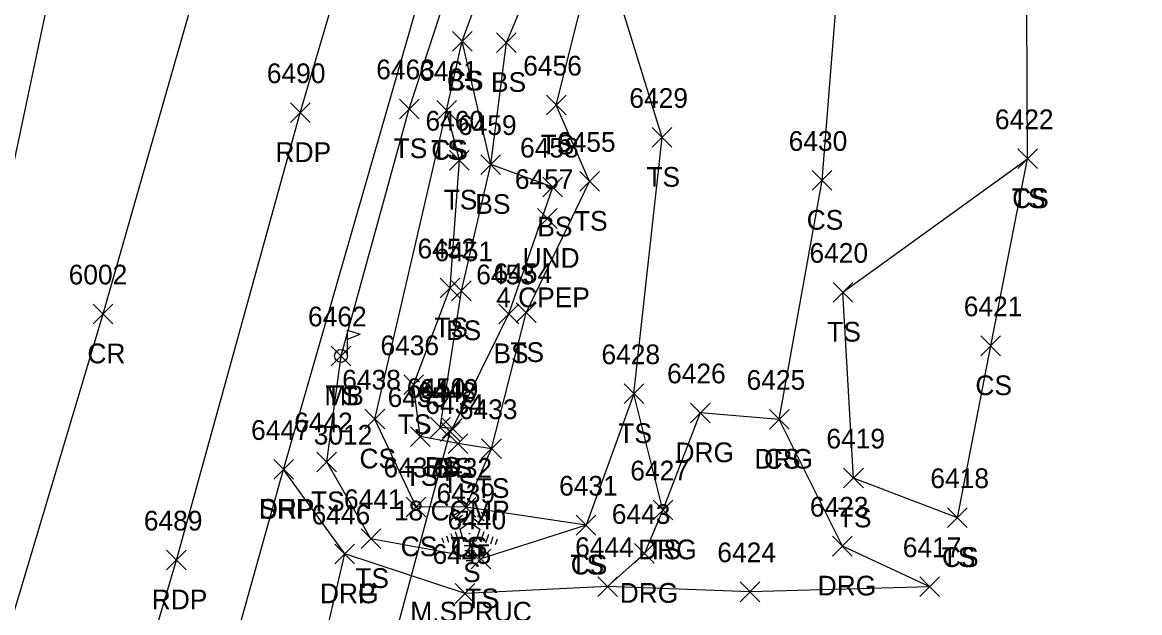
# Model space of a CAD drawing. Extents: x 1443912 to 1445411, y 621446 to 623693.
# Drawn here: x 1444581.9 to 1444695.3, y 621993.5 to 622053.4 of the extents above; entities that cross this region are included whole.
import ezdxf

# ---------------------------------------------------------------- set-up
doc = ezdxf.new("R2010")
doc.units = 0
for name, color, linetype in [('D_A', 7, 'Continuous'), ('D_C', 7, 'Continuous'), ('D_I', 7, 'Continuous'), ('D_TIC', 7, 'Continuous'), ('DCP', 7, 'Continuous'), ('L_A', 7, 'Continuous'), ('L_C', 7, 'Continuous'), ('L_I', 7, 'Continuous'), ('L_TIC', 7, 'Continuous'), ('LELB', 7, 'Continuous'), ('LMB', 7, 'Continuous'), ('LTC', 7, 'Continuous'), ('P_A', 7, 'Continuous'), ('P_I', 7, 'Continuous'), ('P_TIC', 7, 'Continuous'), ('PET', 7, 'Continuous'), ('PRC', 7, 'Continuous'), ('PSP', 7, 'Continuous'), ('R_A', 7, 'Continuous'), ('R_I', 7, 'Continuous'), ('R_TIC', 7, 'Continuous'), ('RDG', 7, 'Continuous'), ('RDP', 7, 'Continuous')]:
    doc.layers.add(name, color=color, linetype=linetype)

msp = doc.modelspace()

# ---------------------------------------------------------------- linework, layer by layer
at = {"layer": 'D_TIC'}
for points in [[(1444634.23, 622032.46), (1444636.23, 622034.46)], [(1444636.23, 622032.46), (1444634.23, 622034.46)], [(1444624.36, 622010.83), (1444626.36, 622012.83)], [(1444626.36, 622010.83), (1444624.36, 622012.83)]]:
    msp.add_lwpolyline(points, dxfattribs=at)
at = {"layer": 'DCP'}
msp.add_lwpolyline([(1444615.47, 621975.13), (1444625.36, 622011.83)], dxfattribs=at)
at = {"layer": 'L_TIC'}
for points in [[(1444625.59, 622050.44), (1444627.59, 622052.44)], [(1444627.59, 622050.44), (1444625.59, 622052.44)], [(1444625.59, 622050.44), (1444627.59, 622052.44)], [(1444627.59, 622050.44), (1444625.59, 622052.44)], [(1444630.06, 622050.3), (1444632.06, 622052.3)], [(1444632.06, 622050.3), (1444630.06, 622052.3)], [(1444620.21, 622043.58), (1444622.21, 622045.58)], [(1444622.21, 622043.58), (1444620.21, 622045.58)], [(1444635.13, 622043.96), (1444637.13, 622045.96)], [(1444637.13, 622043.96), (1444635.13, 622045.96)], [(1444624, 622043.42), (1444626, 622045.42)], [(1444626, 622043.42), (1444624, 622045.42)], [(1444624, 622043.42), (1444626, 622045.42)], [(1444626, 622043.42), (1444624, 622045.42)], [(1444645.86, 622040.68), (1444647.86, 622042.68)], [(1444647.86, 622040.68), (1444645.86, 622042.68)], [(1444625.29, 622038.37), (1444627.29, 622040.37)], [(1444627.29, 622038.37), (1444625.29, 622040.37)], [(1444628.47, 622037.93), (1444630.47, 622039.93)], [(1444630.47, 622037.93), (1444628.47, 622039.93)], [(1444628.47, 622037.93), (1444630.47, 622039.93)], [(1444630.47, 622037.93), (1444628.47, 622039.93)], [(1444682.95, 622038.52), (1444684.95, 622040.52)], [(1444684.95, 622038.52), (1444682.95, 622040.52)], [(1444682.95, 622038.52), (1444684.95, 622040.52)], [(1444684.95, 622038.52), (1444682.95, 622040.52)], [(1444634.76, 622035.64), (1444636.76, 622037.64)], [(1444636.76, 622035.64), (1444634.76, 622037.64)], [(1444638.51, 622036.22), (1444640.51, 622038.22)], [(1444640.51, 622036.22), (1444638.51, 622038.22)], [(1444662.1, 622036.32), (1444664.1, 622038.32)], [(1444664.1, 622036.32), (1444662.1, 622038.32)], [(1444624.35, 622025.41), (1444626.35, 622027.41)], [(1444626.35, 622025.41), (1444624.35, 622027.41)], [(1444625.5, 622025.12), (1444627.5, 622027.12)], [(1444627.5, 622025.12), (1444625.5, 622027.12)], [(1444664.22, 622024.97), (1444666.22, 622026.97)], [(1444666.22, 622024.97), (1444664.22, 622026.97)], [(1444630.31, 622022.78), (1444632.31, 622024.78)], [(1444632.31, 622022.78), (1444630.31, 622024.78)], [(1444632.07, 622022.9), (1444634.07, 622024.9)], [(1444634.07, 622022.9), (1444632.07, 622024.9)], [(1444679.22, 622019.54), (1444681.22, 622021.54)], [(1444681.22, 622019.54), (1444679.22, 622021.54)], [(1444613.28, 622018.52), (1444615.28, 622020.52)], [(1444615.28, 622018.52), (1444613.28, 622020.52)], [(1444620.64, 622015.59), (1444622.64, 622017.59)], [(1444622.64, 622015.59), (1444620.64, 622017.59)], [(1444643.01, 622014.68), (1444645.01, 622016.68)], [(1444645.01, 622014.68), (1444643.01, 622016.68)], [(1444643.01, 622014.68), (1444645.01, 622016.68)], [(1444645.01, 622014.68), (1444643.01, 622016.68)], [(1444616.71, 622012.11), (1444618.71, 622014.11)], [(1444618.71, 622012.11), (1444616.71, 622014.11)], [(1444657.75, 622012.08), (1444659.75, 622014.08)], [(1444659.75, 622012.08), (1444657.75, 622014.08)], [(1444623.35, 622011.26), (1444625.35, 622013.26)], [(1444625.35, 622011.26), (1444623.35, 622013.26)], [(1444624.58, 622011.17), (1444626.58, 622013.17)], [(1444626.58, 622011.17), (1444624.58, 622013.17)], [(1444624.58, 622011.17), (1444626.58, 622013.17)], [(1444626.58, 622011.17), (1444624.58, 622013.17)], [(1444621.32, 622010.34), (1444623.32, 622012.34)], [(1444623.32, 622010.34), (1444621.32, 622012.34)], [(1444625.14, 622009.63), (1444627.14, 622011.63)], [(1444627.14, 622009.63), (1444625.14, 622011.63)], [(1444628.55, 622009.11), (1444630.55, 622011.11)], [(1444630.55, 622009.11), (1444628.55, 622011.11)], [(1444628.55, 622009.11), (1444630.55, 622011.11)], [(1444630.55, 622009.11), (1444628.55, 622011.11)], [(1444611.83, 622007.77), (1444613.83, 622009.77)], [(1444613.83, 622007.77), (1444611.83, 622009.77)], [(1444665.29, 622006.13), (1444667.29, 622008.13)], [(1444667.29, 622006.13), (1444665.29, 622008.13)], [(1444620.9, 622003.2), (1444622.9, 622005.2)], [(1444622.9, 622003.2), (1444620.9, 622005.2)], [(1444625.96, 622003.16), (1444627.96, 622005.16)], [(1444627.96, 622003.16), (1444625.96, 622005.16)], [(1444625.96, 622003.16), (1444627.96, 622005.16)], [(1444627.96, 622003.16), (1444625.96, 622005.16)], [(1444645.95, 622002.89), (1444647.95, 622004.89)], [(1444647.95, 622002.89), (1444645.95, 622004.89)], [(1444675.83, 622002.11), (1444677.83, 622004.11)], [(1444677.83, 622002.11), (1444675.83, 622004.11)], [(1444675.83, 622002.11), (1444677.83, 622004.11)], [(1444677.83, 622002.11), (1444675.83, 622004.11)], [(1444638.15, 622001.35), (1444640.15, 622003.35)], [(1444640.15, 622001.35), (1444638.15, 622003.35)], [(1444638.15, 622001.35), (1444640.15, 622003.35)], [(1444640.15, 622001.35), (1444638.15, 622003.35)], [(1444616.32, 621999.98), (1444618.32, 622001.98)], [(1444618.32, 621999.98), (1444616.32, 622001.98)], [(1444627.48, 621997.92), (1444629.48, 621999.92)], [(1444629.48, 621997.92), (1444627.48, 621999.92)]]:
    msp.add_lwpolyline(points, dxfattribs=at)
at = {"layer": 'LELB'}
for points in [[(1444644.01, 622015.68), (1444639.15, 622002.35), (1444628.48, 621998.92), (1444617.32, 622000.98), (1444612.83, 622008.77), (1444614.28, 622019.52), (1444621.21, 622044.58), (1444632.46, 622078.99), (1444638.16, 622089.94), (1444643.22, 622097.1), (1444651.63, 622103.86), (1444671.66, 622102.03), (1444685.79, 622100.42), (1444698.09, 622093.83)], [(1444625.58, 622012.17), (1444631.31, 622023.78), (1444635.76, 622036.64), (1444629.47, 622038.93), (1444631.06, 622051.3), (1444637.11, 622065.66), (1444641.14, 622072.33), (1444643.26, 622087.97), (1444647.46, 622094.16), (1444644.74, 622096.3)], [(1444626.96, 622004.16), (1444629.55, 622010.11), (1444633.07, 622023.9), (1444639.51, 622037.22), (1444636.13, 622044.96), (1444640.48, 622062.36), (1444645.82, 622067.12), (1444646.95, 622073.59), (1444654.32, 622091.95), (1444676.1, 622093.86), (1444692.82, 622085.1)], [(1444625.58, 622012.17), (1444624.35, 622012.26), (1444626.5, 622026.12), (1444629.47, 622038.93), (1444626.59, 622051.44), (1444636.28, 622077.9), (1444640.86, 622088.53)], [(1444658.75, 622013.08), (1444663.1, 622037.32), (1444665.26, 622064.61)], [(1444646.95, 622003.89), (1444644.01, 622015.68), (1444646.86, 622041.68), (1444640.48, 622062.36)], [(1444676.83, 622003.11), (1444680.22, 622020.54), (1444683.95, 622039.52), (1444683.84, 622062.37)], [(1444639.15, 622002.35), (1444626.96, 622004.16), (1444621.9, 622004.2), (1444617.71, 622013.11), (1444625, 622044.42), (1444626.59, 622051.44)], [(1444629.55, 622010.11), (1444626.14, 622010.63), (1444622.32, 622011.34), (1444621.64, 622016.59), (1444625.35, 622026.41), (1444626.29, 622039.37), (1444625, 622044.42)], [(1444676.83, 622003.11), (1444666.29, 622007.13), (1444665.22, 622025.97), (1444683.95, 622039.52)]]:
    msp.add_lwpolyline(points, dxfattribs=at)
at = {"layer": 'LMB'}
for p, q in [((1444614.93, 622022.12), (1444616.23, 622021.74)), ((1444614.94, 622019.53), (1444614.94, 622022.12)), ((1444614.94, 622021.22), (1444616.22, 622021.73)), ((1444614.28, 622019.52), (1444614.28, 622019.52))]:
    msp.add_line(p, q, dxfattribs=at)
msp.add_circle((1444614.28, 622019.52), 0.656, dxfattribs=at)
at = {"layer": 'LTC'}
for p, q in [((1444625.48, 622003.79), (1444625.84, 622004.04)), ((1444625.69, 622003.32), (1444626.22, 622003.7)), ((1444628.51, 622003.68), (1444629.06, 622003.28)), ((1444628.88, 622004.03), (1444629.3, 622003.72)), ((1444625.9, 622002.85), (1444626.61, 622003.37)), ((1444626.11, 622002.39), (1444626.99, 622003.03)), ((1444626.34, 622001.93), (1444627.35, 622002.67)), ((1444627.35, 622002.67), (1444628.35, 622001.94)), ((1444627.77, 622002.98), (1444628.58, 622002.39)), ((1444628.14, 622003.33), (1444628.82, 622002.84)), ((1444625.43, 622001.5), (1444625.7, 622000.66)), ((1444625.88, 622001.71), (1444626.21, 622000.7)), ((1444626.34, 622001.93), (1444626.72, 622000.74)), ((1444628.35, 622001.94), (1444627.96, 622000.74)), ((1444628.78, 622001.67), (1444628.45, 622000.63)), ((1444629.23, 622001.42), (1444628.94, 622000.54)), ((1444624.52, 622001.06), (1444624.67, 622000.6)), ((1444624.97, 622001.28), (1444625.18, 622000.63)), ((1444627.96, 622000.74), (1444626.72, 622000.74)), ((1444627.92, 622000.24), (1444626.77, 622000.24)), ((1444629.67, 622001.17), (1444629.44, 622000.44)), ((1444630.12, 622000.92), (1444629.93, 622000.35)), ((1444627.83, 621999.74), (1444626.84, 621999.74)), ((1444627.75, 621999.24), (1444626.92, 621999.24)), ((1444627.67, 621998.74), (1444626.99, 621998.74))]:
    msp.add_line(p, q, dxfattribs=at)
at = {"layer": 'P_TIC'}
for points in [[(1444609.14, 622043.19), (1444611.14, 622045.19)], [(1444611.14, 622043.19), (1444609.14, 622045.19)], [(1444589.11, 622022.77), (1444591.11, 622024.77)], [(1444591.11, 622022.77), (1444589.11, 622024.77)], [(1444607.45, 622007), (1444609.45, 622009)], [(1444609.45, 622007), (1444607.45, 622009)], [(1444596.58, 621997.81), (1444598.58, 621999.81)], [(1444598.58, 621997.81), (1444596.58, 621999.81)]]:
    msp.add_lwpolyline(points, dxfattribs=at)
at = {"layer": 'PET'}
for points in [[(1444707.78, 622511.05), (1444700.03, 622482.58), (1444691.73, 622453.67), (1444679.73, 622411.23), (1444667.69, 622368.84), (1444653.08, 622317.67), (1444637.74, 622256.92), (1444626.42, 622209.58), (1444619.02, 622182.67), (1444605.37, 622130.08), (1444589.4, 622078.61), (1444578.44, 622026.86), (1444565.52, 621990.05), (1444556.87, 621958.17), (1444542.16, 621907.74), (1444529.8, 621863.07), (1444511.99, 621799.88), (1444498.16, 621751.76), (1444483.13, 621697.3), (1444470.84, 621653.16), (1444463.41, 621627.34), (1444449.07, 621575.52), (1444430.26, 621508.83), (1444421.17, 621471.46)], [(1444444.37, 621464.94), (1444461.94, 621522.87), (1444475.59, 621570.55), (1444487.99, 621616.26), (1444502.92, 621667.73), (1444516.83, 621718.16), (1444526.41, 621751.49), (1444537.28, 621789.32), (1444558.59, 621865), (1444573.59, 621917.93), (1444597.58, 621998.81), (1444610.14, 622044.19), (1444623.48, 622089.5), (1444632.2, 622118.09)]]:
    msp.add_lwpolyline(points, dxfattribs=at)
at = {"layer": 'PRC'}
msp.add_lwpolyline([(1444618.32, 622127.38), (1444604.97, 622075.74), (1444590.11, 622023.77), (1444578.57, 621985.29), (1444569.73, 621954.72), (1444555.25, 621903.96), (1444542.35, 621859.58), (1444524.46, 621796.02), (1444511.19, 621747.94), (1444495.68, 621693.61), (1444483.2, 621649.28), (1444475.93, 621623.97), (1444461.82, 621572.2), (1444443.22, 621505.41), (1444432.75, 621467.94)], dxfattribs=at)
at = {"layer": 'PSP'}
msp.add_lwpolyline([(1444455.66, 621462.75), (1444472.05, 621519.48), (1444485.13, 621568.3), (1444497.88, 621612.67), (1444505.4, 621638.58), (1444519.01, 621689.59), (1444525.59, 621713.97), (1444535.94, 621748.74), (1444541.51, 621770.15), (1444550.94, 621803.78), (1444567.68, 621862.81), (1444582.56, 621915.85), (1444597.67, 621969.6), (1444608.45, 622008), (1444628.13, 622076.36), (1444639.3, 622115.36)], dxfattribs=at)
at = {"layer": 'R_TIC'}
for points in [[(1444649.73, 622012.74), (1444651.73, 622014.74)], [(1444651.73, 622012.74), (1444649.73, 622014.74)], [(1444657.75, 622012.08), (1444659.75, 622014.08)], [(1444659.75, 622012.08), (1444657.75, 622014.08)], [(1444607.45, 622007), (1444609.45, 622009)], [(1444609.45, 622007), (1444607.45, 622009)], [(1444645.95, 622002.89), (1444647.95, 622004.89)], [(1444647.95, 622002.89), (1444645.95, 622004.89)], [(1444613.65, 621998.43), (1444615.65, 622000.43)], [(1444615.65, 621998.43), (1444613.65, 622000.43)], [(1444613.65, 621998.43), (1444615.65, 622000.43)], [(1444615.65, 621998.43), (1444613.65, 622000.43)], [(1444644.07, 621998.48), (1444646.07, 622000.48)], [(1444646.07, 621998.48), (1444644.07, 622000.48)], [(1444664.17, 621999.22), (1444666.17, 622001.22)], [(1444666.17, 621999.22), (1444664.17, 622001.22)], [(1444640.34, 621995.12), (1444642.34, 621997.12)], [(1444642.34, 621995.12), (1444640.34, 621997.12)], [(1444640.34, 621995.12), (1444642.34, 621997.12)], [(1444642.34, 621995.12), (1444640.34, 621997.12)], [(1444673.03, 621995.1), (1444675.03, 621997.1)], [(1444675.03, 621995.1), (1444673.03, 621997.1)], [(1444673.03, 621995.1), (1444675.03, 621997.1)], [(1444675.03, 621995.1), (1444673.03, 621997.1)], [(1444625.87, 621994.42), (1444627.87, 621996.42)], [(1444627.87, 621994.42), (1444625.87, 621996.42)], [(1444654.77, 621994.59), (1444656.77, 621996.59)], [(1444656.77, 621994.59), (1444654.77, 621996.59)]]:
    msp.add_lwpolyline(points, dxfattribs=at)
at = {"layer": 'RDG'}
for points in [[(1444674.03, 621996.1), (1444665.17, 622000.22), (1444658.75, 622013.08), (1444650.73, 622013.74), (1444646.95, 622003.89), (1444645.07, 621999.48), (1444641.34, 621996.12)], [(1444674.03, 621996.1), (1444655.77, 621995.59), (1444641.34, 621996.12), (1444626.87, 621995.42), (1444614.65, 621999.43)]]:
    msp.add_lwpolyline(points, dxfattribs=at)
at = {"layer": 'RDP'}
msp.add_lwpolyline([(1444597.67, 621969.6), (1444601.78, 621979.23), (1444611.81, 621987.27), (1444614.65, 621999.43), (1444608.45, 622008)], dxfattribs=at)

# ---------------------------------------------------------------- texts
at = {"layer": 'D_A'}
for s, p in [('UND', (1444632.7, 622028.46)), ('P', (1444624.74, 622006.83))]:
    msp.add_text(s, height=2, dxfattribs=at).set_placement(p)
at = {"layer": 'D_C'}
for s, p in [('4 CPEP', (1444630.02, 622024.46)), ('18 CGMP', (1444619.65, 622002.83))]:
    msp.add_text(s, height=2, dxfattribs=at).set_placement(p)
at = {"layer": 'D_I'}
for s, p in [('6457', (1444631.92, 622036.46)), ('6448', (1444622.05, 622014.83))]:
    msp.add_text(s, height=2, dxfattribs=at).set_placement(p)
at = {"layer": 'L_A'}
for s, p in [('CS', (1444625.03, 622046.44)), ('BS', (1444625.03, 622046.44)), ('BS', (1444629.5, 622046.3)), ('TS', (1444619.62, 622039.58)), ('TS', (1444623.41, 622039.42)), ('CS', (1444623.44, 622039.42)), ('TS', (1444634.54, 622039.96)), ('TS', (1444645.27, 622036.68)), ('TS', (1444682.36, 622034.52)), ('CS', (1444682.39, 622034.52)), ('TS', (1444624.7, 622034.37)), ('BS', (1444627.91, 622033.93)), ('BS', (1444627.91, 622033.93)), ('TS', (1444637.92, 622032.22)), ('CS', (1444661.54, 622032.32)), ('BS', (1444634.2, 622031.64)), ('TS', (1444623.75, 622021.41)), ('BS', (1444624.94, 622021.12)), ('TS', (1444663.62, 622020.97)), ('BS', (1444629.75, 622018.78)), ('TS', (1444631.47, 622018.9)), ('CS', (1444678.66, 622015.54)), ('TS', (1444612.69, 622014.52)), ('MB', (1444612.59, 622014.52)), ('TS', (1444620.05, 622011.59)), ('TS', (1444642.42, 622010.68)), ('TS', (1444642.42, 622010.68)), ('CS', (1444616.15, 622008.11)), ('BS', (1444622.79, 622007.26)), ('CS', (1444657.19, 622008.08)), ('TS', (1444620.73, 622006.34)), ('BS', (1444624.03, 622007.17)), ('BS', (1444624.03, 622007.17)), ('TS', (1444624.55, 622005.63)), ('TS', (1444627.96, 622005.11)), ('TS', (1444627.96, 622005.11)), ('TS', (1444611.23, 622003.77)), ('TS', (1444664.7, 622002.13)), ('CS', (1444620.34, 621999.2)), ('TS', (1444625.37, 621999.16)), ('CS', (1444625.41, 621999.16)), ('TS', (1444645.36, 621998.89)), ('TS', (1444637.56, 621997.35)), ('CS', (1444637.59, 621997.35)), ('TS', (1444675.24, 621998.11)), ('CS', (1444675.27, 621998.11)), ('TS', (1444615.73, 621995.98)), ('S', (1444626.67, 621996.58)), ('TS', (1444626.89, 621993.92))]:
    msp.add_text(s, height=2, dxfattribs=at).set_placement(p)
at = {"layer": 'L_C'}
for s, p in [('3012', (1444611.51, 622010.52)), ('M.SPRUC', (1444621.31, 621992.58))]:
    msp.add_text(s, height=2, dxfattribs=at).set_placement(p)
at = {"layer": 'L_I'}
for s, p in [('6463', (1444617.85, 622047.58)), ('6461', (1444622.21, 622047.42)), ('6461', (1444622.21, 622047.42)), ('6456', (1444632.77, 622047.96)), ('6429', (1444643.54, 622044.68)), ('6422', (1444680.64, 622042.52)), ('6422', (1444680.64, 622042.52)), ('6460', (1444622.85, 622042.37)), ('6459', (1444626.15, 622041.93)), ('6459', (1444626.15, 622041.93)), ('6455', (1444636.2, 622040.22)), ('6430', (1444659.71, 622040.32)), ('6458', (1444632.45, 622039.64)), ('6452', (1444622.04, 622029.41)), ('6451', (1444623.76, 622029.12)), ('6420', (1444661.82, 622028.97)), ('6453', (1444628, 622026.78)), ('6454', (1444629.76, 622026.9)), ('6421', (1444677.48, 622023.54)), ('6462', (1444610.93, 622022.52)), ('6462', (1444610.93, 622022.52)), ('6436', (1444618.28, 622019.59)), ('6428', (1444640.71, 622018.68)), ('6428', (1444640.71, 622018.68)), ('6438', (1444614.4, 622016.11)), ('6450', (1444620.95, 622015.26)), ('6425', (1444655.44, 622016.08)), ('6435', (1444619.01, 622014.34)), ('6449', (1444622.27, 622015.17)), ('6449', (1444622.27, 622015.17)), ('6434', (1444622.83, 622013.63)), ('6433', (1444626.24, 622013.11)), ('6433', (1444626.24, 622013.11)), ('6442', (1444609.52, 622011.77)), ('6419', (1444663.54, 622010.13)), ('6437', (1444618.59, 622007.2)), ('6432', (1444623.66, 622007.16)), ('6432', (1444623.66, 622007.16)), ('6427', (1444643.64, 622006.89)), ('6431', (1444636.41, 622005.35)), ('6431', (1444636.41, 622005.35)), ('6418', (1444674.09, 622006.11)), ('6418', (1444674.09, 622006.11)), ('6441', (1444614.58, 622003.98)), ('6439', (1444623.97, 622004.58)), ('6440', (1444625.09, 622001.92))]:
    msp.add_text(s, height=2, dxfattribs=at).set_placement(p)
at = {"layer": 'LTC'}
msp.add_text('.', height=1.04, rotation=270, dxfattribs=at).set_placement((1444627.23, 622001.68))
at = {"layer": 'P_A'}
for s, p in [('RDP', (1444607.63, 622039.19)), ('CR', (1444588.54, 622018.77)), ('SHP', (1444605.99, 622003)), ('RDP', (1444595.07, 621993.81))]:
    msp.add_text(s, height=2, dxfattribs=at).set_placement(p)
at = {"layer": 'P_I'}
for s, p in [('6490', (1444606.75, 622047.19)), ('6002', (1444586.64, 622026.77)), ('6447', (1444605.15, 622011)), ('6489', (1444594.27, 622001.81))]:
    msp.add_text(s, height=2, dxfattribs=at).set_placement(p)
at = {"layer": 'R_A'}
for s, p in [('DRG', (1444648.22, 622008.74)), ('DRG', (1444656.23, 622008.08)), ('DRP', (1444605.94, 622003)), ('DRG', (1444644.44, 621998.89)), ('DRG', (1444662.65, 621995.22)), ('DRG', (1444612.14, 621994.43)), ('DRP', (1444612.14, 621994.43)), ('DRG', (1444642.56, 621994.48))]:
    msp.add_text(s, height=2, dxfattribs=at).set_placement(p)
at = {"layer": 'R_I'}
for s, p in [('6426', (1444647.37, 622016.74)), ('6425', (1444655.44, 622016.08)), ('6447', (1444605.15, 622011)), ('6427', (1444643.64, 622006.89)), ('6423', (1444661.86, 622003.22)), ('6446', (1444611.29, 622002.43)), ('6446', (1444611.29, 622002.43)), ('6443', (1444641.76, 622002.48)), ('6445', (1444623.57, 621998.42)), ('6444', (1444638.04, 621999.12)), ('6444', (1444638.04, 621999.12)), ('6424', (1444652.47, 621998.59)), ('6417', (1444671.29, 621999.1)), ('6417', (1444671.29, 621999.1))]:
    msp.add_text(s, height=2, dxfattribs=at).set_placement(p)

doc.saveas('drawing.dxf')
